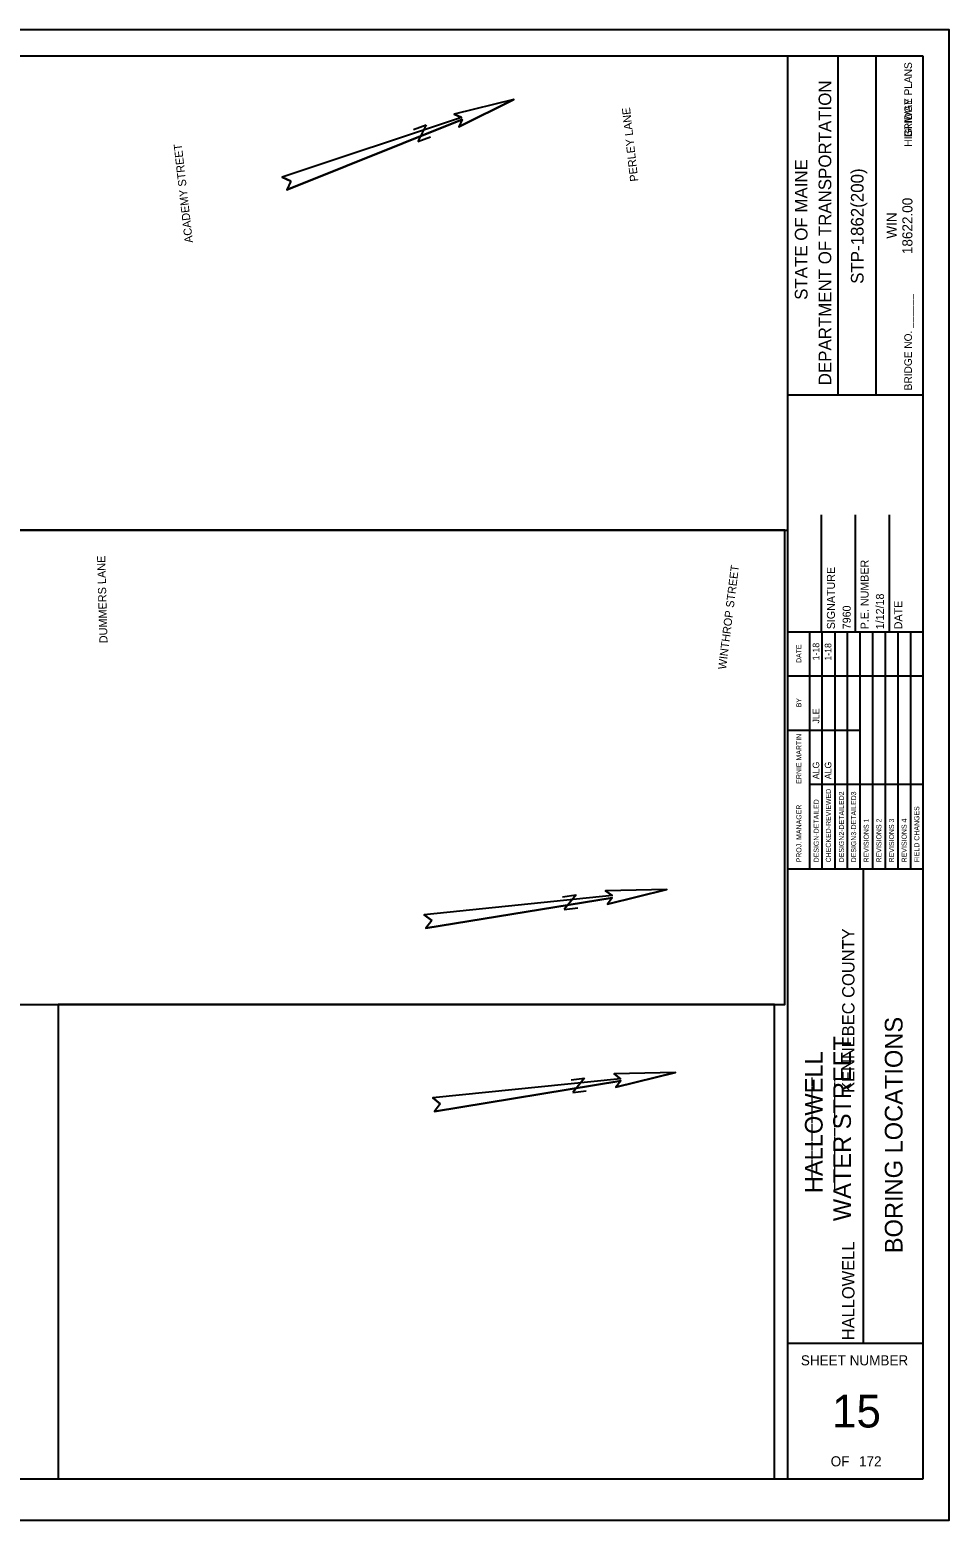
# Model space of a CAD drawing. Extents: x 0 to 850, y 0 to 550.
# Drawn here: x 511 to 850, y 0 to 550 of the extents above; entities that cross this region are included whole.
import ezdxf

# ---------------------------------------------------------------- set-up
doc = ezdxf.new("R2010")
doc.units = 0
for name, color, linetype in [('BORDER', 7, 'Continuous'), ('BRIDGE_TITLE', 7, 'Continuous'), ('D_Roadway_Centerline_Text', 7, 'Continuous'), ('Default', 7, 'Continuous'), ('H_V CONTROLS', 7, 'Continuous'), ('HIGHWAY_TITLE', 7, 'Continuous'), ('PLOT BOUNDARY', 7, 'Continuous')]:
    doc.layers.add(name, color=color, linetype=linetype)

msp = doc.modelspace()

# ---------------------------------------------------------------- linework, layer by layer
at = {"layer": 'BORDER'}
for p, q in [((840.33, 540.24), (40.33, 540.24)), ((790.33, 15.26), (790.33, 540.26)), ((808.97, 415.23), (808.97, 540.23)), ((822.95, 415.23), (822.95, 540.23)), ((840.33, 15.26), (840.33, 540.26)), ((790.34, 415.22), (840.33, 415.22)), ((802.83, 327.76), (802.83, 371)), ((815.33, 327.76), (815.33, 371)), ((827.83, 327.76), (827.83, 371)), ((790.33, 327.76), (840.33, 327.76)), ((790.33, 240.26), (840.33, 240.26)), ((818.29, 65.26), (818.29, 240.26)), ((790.33, 65.26), (840.33, 65.26)), ((40.33, 15.24), (840.33, 15.24))]:
    msp.add_line(p, q, dxfattribs=at)
for points in [[(798.41, 311.51), (798.41, 327.76)], [(803.07, 240.27), (803.07, 327.76)], [(807.73, 327.76), (807.73, 240.27)], [(812.39, 240.27), (812.39, 327.76)], [(817.04, 240.27), (817.04, 327.76)], [(821.7, 240.27), (821.7, 327.76)], [(826.36, 240.27), (826.36, 327.76)], [(831.02, 240.27), (831.02, 327.76)], [(835.68, 240.27), (835.68, 327.76)], [(798.41, 240.27), (798.41, 324.23)], [(790.33, 311.51), (840.33, 311.51)], [(790.33, 291.51), (798.41, 291.51)], [(798.41, 291.51), (817.04, 291.51)], [(798.41, 271.51), (840.33, 271.51)]]:
    msp.add_lwpolyline(points, dxfattribs=at)
at = {"layer": 'Default'}
for points in [[(40.33, 365.26), (790.33, 365.26), (790.33, 540.24), (40.33, 540.24)], [(40.33, 190.26), (789.25, 190.26), (789.25, 365.26), (40.33, 365.26)], [(521.22, 15.26), (785.39, 15.26), (785.39, 190.26), (521.22, 190.26)]]:
    msp.add_lwpolyline(points, close=True, dxfattribs=at)
at = {"layer": 'H_V CONTROLS'}
for p, q in [((689.26, 524.17), (667.27, 518.79)), ((689.26, 524.17), (668.99, 514.09)), ((669.99, 517.53), (603.88, 495.59)), ((669.99, 517.53), (667.27, 518.79)), ((670.25, 516.8), (605.6, 490.9)), ((670.25, 516.8), (668.99, 514.09)), ((607.09, 494.1), (603.88, 495.59)), ((607.09, 494.1), (605.6, 490.9)), ((745.77, 232.75), (723.14, 232.26)), ((725.51, 230.45), (723.14, 232.26)), ((745.77, 232.75), (723.8, 227.31)), ((725.51, 230.45), (656.23, 223.37)), ((725.61, 229.68), (656.88, 218.41)), ((725.61, 229.68), (723.8, 227.31)), ((659.03, 221.22), (656.23, 223.37)), ((659.03, 221.22), (656.88, 218.41)), ((748.91, 165.16), (726.28, 164.67)), ((748.91, 165.16), (726.94, 159.72)), ((728.65, 162.86), (659.36, 155.78)), ((728.75, 162.09), (660.02, 150.82)), ((728.65, 162.86), (726.28, 164.67)), ((728.75, 162.09), (726.94, 159.72)), ((662.17, 153.63), (659.36, 155.78)), ((662.17, 153.63), (660.02, 150.82))]:
    msp.add_line(p, q, dxfattribs=at)
for points in [[(607.09, 494.1), (605.6, 490.9), (670.25, 516.8), (668.99, 514.09), (689.26, 524.17), (667.27, 518.79), (669.99, 517.53), (603.88, 495.59), (607.09, 494.1)], [(652.3, 513.16), (656.99, 514.88)], [(656.99, 514.88), (653.92, 508.72)], [(653.92, 508.72), (658.62, 510.44)], [(659.03, 221.22), (656.88, 218.41), (725.61, 229.68), (723.8, 227.31), (745.77, 232.75), (723.14, 232.26), (725.51, 230.45), (656.23, 223.37), (659.03, 221.22)], [(707.29, 230.02), (712.25, 230.68)], [(712.25, 230.68), (707.92, 225.33)], [(707.92, 225.33), (712.87, 225.99)], [(662.17, 153.63), (660.02, 150.82), (728.75, 162.09), (726.94, 159.72), (748.91, 165.16), (726.28, 164.67), (728.65, 162.86), (659.36, 155.78), (662.17, 153.63)], [(710.43, 162.43), (715.39, 163.09)], [(715.39, 163.09), (711.06, 157.75)], [(711.06, 157.75), (716.01, 158.4)]]:
    msp.add_lwpolyline(points, dxfattribs=at)
at = {"layer": 'PLOT BOUNDARY'}
msp.add_lwpolyline([(-0.13, -0.05), (849.87, -0.05), (849.87, 549.95), (-0.13, 549.95)], close=True, dxfattribs=at)

# ---------------------------------------------------------------- texts
at = {"layer": 'BORDER'}
for s, height, p in [('DEPARTMENT OF TRANSPORTATION', 4.6588, (806.37, 418.77)), ('STATE OF MAINE', 4.6588, (797.61, 450.3)), ('STP-1862(200)', 4.6588, (818.29, 456.21)), ('18622.00', 3.726, (836.31, 467.18)), ('WIN', 3.726, (830.52, 472.89)), ('P.E. NUMBER', 2.9528, (820.14, 328.72)), ('SIGNATURE', 2.953, (807.73, 328.72)), ('1/12/18', 2.953, (825.8, 328.72)), ('7960', 2.953, (813.54, 328.72)), ('DATE', 2.953, (832.54, 328.72)), ('DATE', 1.857, (795.35, 316.29)), ('1-18', 2.423, (801.95, 317.25)), ('1-18', 2.423, (806.42, 317.14)), ('BY', 1.857, (795.35, 299.93)), ('JLE', 2.423, (801.95, 293.93)), ('ERNIE MARTIN', 1.8637, (795.35, 271.72)), ('ALG', 2.423, (801.95, 273.38)), ('ALG', 2.423, (806.42, 273.38)), ('DESIGN-DETAILED', 1.8637, (801.76, 242.7)), ('CHECKED-REVIEWED', 1.8637, (806.24, 242.7)), ('DESIGN2-DETAILED2', 1.8637, (811.08, 242.7)), ('DESIGN3-DETAILED3', 1.8637, (815.55, 242.7)), ('PROJ. MANAGER', 1.8637, (795.35, 242.7)), ('FIELD CHANGES', 1.8637, (838.85, 242.7)), ('REVISIONS 1', 1.8637, (820.21, 242.7)), ('REVISIONS 2', 1.8637, (824.87, 242.7)), ('REVISIONS 3', 1.8637, (829.53, 242.7)), ('REVISIONS 4', 1.8637, (834.19, 242.7)), ('BORING LOCATIONS', 6.5214, (832.66, 98.47))]:
    msp.add_text(s, height=height, rotation=90, dxfattribs=at).set_placement(p)
for s, height, p in [('SHEET NUMBER', 3.7264, (795.16, 57.08)), ('15', 12.097, (806.69, 34.16)), ('OF', 3.726, (806.17, 19.81)), ('172', 3.726, (816.61, 19.81))]:
    msp.add_text(s, height=height, dxfattribs=at).set_placement(p)
at = {"layer": 'BRIDGE_TITLE'}
for s, height, p in [('BRIDGE PLANS', 2.795, (836.12, 510.37)), ('BRIDGE NO. ______', 2.795, (836.12, 416.9)), ('KENNEBEC COUNTY', 4.5358, (814.93, 157.65)), ('_____________', 4.5358, (806.55, 121.2)), ('___________', 4.5358, (798.16, 126.17)), ('HALLOWELL', 4.536, (814.93, 66.36))]:
    msp.add_text(s, height=height, rotation=90, dxfattribs=at).set_placement(p)
at = {"layer": 'D_Roadway_Centerline_Text'}
for s, rotation, p in [('PERLEY LANE', 96.488, (735.22, 494.14)), ('ACADEMY STREET', 96.488, (570.95, 471.47)), ('DUMMERS LANE', 91.5497, (539.45, 323.61)), ('WINTHROP STREET', 82.8497, (767.56, 313.77))]:
    msp.add_text(s, height=3, rotation=rotation, dxfattribs=at).set_placement(p)
at = {"layer": 'HIGHWAY_TITLE'}
for s, height, p in [('HIGHWAY PLANS', 2.795, (836.12, 506.82)), ('WATER STREET', 6.5214, (813.63, 110.3)), ('HALLOWELL', 6.521, (803.19, 120.63))]:
    msp.add_text(s, height=height, rotation=90, dxfattribs=at).set_placement(p)

doc.saveas('drawing.dxf')
